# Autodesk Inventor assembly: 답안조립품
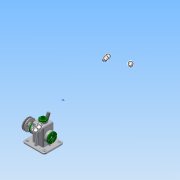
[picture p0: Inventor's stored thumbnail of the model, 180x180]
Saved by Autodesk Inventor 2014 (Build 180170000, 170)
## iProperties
Created: 2015-12
Part Number: 답안조립품
Document SubType Name: Assembly
Designer: Administrator
Author: Administrator
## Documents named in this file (19)
- C:\Documents and Settings\Administrator\바탕 화면\451225V1004\답안조립품.iam
- C:\Documents and Settings\Administrator\바탕 화면\451225V1004\본체.ipt
- C:\Documents and Settings\Administrator\바탕 화면\451225V1004\V-벨트풀리.ipt
- C:\Documents and Settings\Administrator\바탕 화면\451225V1004\고정핀.ipt
- C:\Documents and Settings\Administrator\바탕 화면\451225V1004\뒤커버.ipt
- C:\Documents and Settings\Administrator\바탕 화면\451225V1004\링크.ipt
- C:\Documents and Settings\Administrator\바탕 화면\451225V1004\멈춤링 6 x 5.ipt
- C:\Documents and Settings\Administrator\바탕 화면\451225V1004\멈춤링 15 x 1.ipt
- C:\Documents and Settings\Administrator\바탕 화면\451225V1004\베어링 15 x 35 x 11.ipt
- C:\Documents and Settings\Administrator\바탕 화면\451225V1004\볼트 M3 x 8.ipt
- C:\Documents and Settings\Administrator\바탕 화면\451225V1004\볼트 M4 x 10.ipt
- C:\Documents and Settings\Administrator\바탕 화면\451225V1004\볼트 M6 x 12.ipt
- C:\Documents and Settings\Administrator\바탕 화면\451225V1004\상부부시.ipt
- C:\Documents and Settings\Administrator\바탕 화면\451225V1004\슬라이드바.ipt
- C:\Documents and Settings\Administrator\바탕 화면\451225V1004\앞커버.ipt
- C:\Documents and Settings\Administrator\바탕 화면\451225V1004\오일실 15 25 7.ipt
- C:\Documents and Settings\Administrator\바탕 화면\451225V1004\와셔.ipt
- C:\Documents and Settings\Administrator\바탕 화면\451225V1004\키 5 x 5 x 14.ipt
- C:\Documents and Settings\Administrator\바탕 화면\451225V1004\편심축.ipt
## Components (15 placed, 5 different names)
1. V-벨트풀리:1 — 각도:2
2. 고정핀:1
3. ISO 4018 M6 x 12:1
4. ISO 4762 M3 x 8:1
5. ISO 4762 M3 x 8:2
6. ISO 4762 M3 x 8:3
7. ISO 4762 M3 x 8:4
8. ISO 4762 M4 x 10:1
9. ISO 4762 M4 x 10:2
10. ISO 4762 M4 x 10:3
11. ISO 4762 M4 x 10:4
12. ISO 4762 M4 x 10:5
13. ISO 4762 M4 x 10:6
14. ISO 4762 M4 x 10:7
15. ISO 4762 M4 x 10:8
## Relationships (1: Angle 1)
- 각도:2 [Angle]: V-벨트풀리:1
